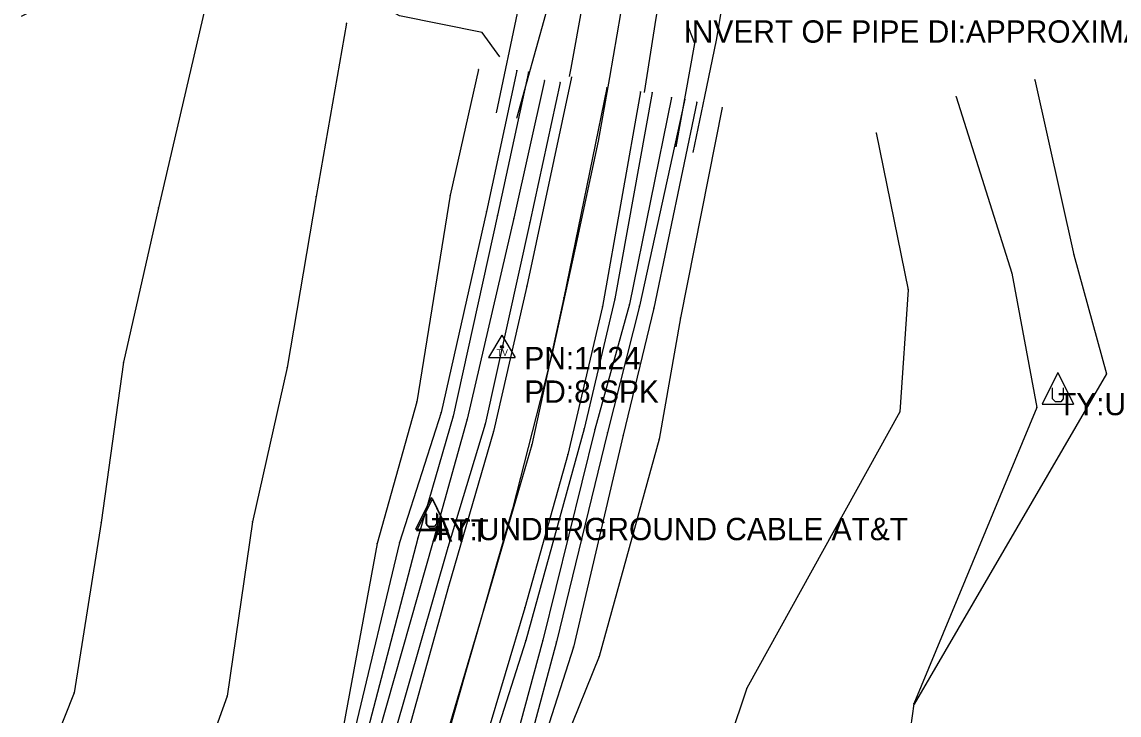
# Model space of a CAD drawing. Extents: x 976456 to 985170, y 1525951 to 1527080.
# Drawn here: x 977697.7 to 977943.1, y 1526175.1 to 1526330.3 of the extents above; entities that cross this region are included whole.
import ezdxf

# ---------------------------------------------------------------- set-up
doc = ezdxf.new("R2010")
doc.units = 0
for name, color, linetype in [('S_BREAKLINE', 7, 'Continuous'), ('S_CROSS_DRAIN_ANNOT', 7, 'Continuous'), ('S_DITCHLINE', 7, 'Continuous'), ('S_EDGE_PAVEMENT', 7, 'Continuous'), ('S_GRD_PT_SYM', 7, 'Continuous'), ('S_PAVEMENT_CROWN', 7, 'Continuous'), ('S_RDW_PT_SYM', 7, 'Continuous'), ('S_SECONDARY_CTL', 7, 'Continuous'), ('S_SECONDARY_CTL_ANNOT', 7, 'Continuous'), ('S_UNDERGROUND_CABLE', 7, 'Continuous'), ('S_UTILITY_POLE_ANNOT', 7, 'Continuous')]:
    doc.layers.add(name, color=color, linetype=linetype)

msp = doc.modelspace()

# ---------------------------------------------------------------- linework, layer by layer
at = {"layer": 'S_BREAKLINE'}
for p, q in [((977740.93, 1526343.34), (977728.22, 1526288.65)), ((977770.28, 1526329.98), (977763.49, 1526291.2)), ((977799.79, 1526319.61), (977793.5, 1526291.46)), ((977814.56, 1526317.14), (977807.69, 1526286.32)), ((977818.08, 1526316.7), (977811.28, 1526285.4)), ((977924.29, 1526317.31), (977933.02, 1526278.16)), ((977838.69, 1526314.51), (977830.29, 1526268.27)), ((977843.01, 1526313.39), (977833.6, 1526267.06)), ((977906.65, 1526313.53), (977919.15, 1526274.05)), ((977854.34, 1526311.09), (977845, 1526264.01)), ((977888.81, 1526305.43), (977895.95, 1526270.32)), ((977763.49, 1526291.2), (977756.99, 1526252.94)), ((977793.5, 1526291.46), (977786.04, 1526245.22)), ((977728.22, 1526288.65), (977720.44, 1526254.08)), ((977807.69, 1526286.32), (977797.28, 1526241.33)), ((977811.28, 1526285.4), (977801.34, 1526240.24)), ((977933.02, 1526278.16), (977940.3, 1526251.52)), ((977919.15, 1526274.05), (977924.73, 1526243.96)), ((977895.95, 1526270.32), (977894.08, 1526242.98)), ((977830.29, 1526268.27), (977823.44, 1526239.18)), ((977833.6, 1526267.06), (977825.83, 1526239.07)), ((977845, 1526264.01), (977840.27, 1526236.87)), ((977720.44, 1526254.08), (977715.44, 1526218.25)), ((977756.99, 1526252.94), (977749.27, 1526218.38)), ((977940.3, 1526251.52), (977897.24, 1526177.52)), ((977786.04, 1526245.22), (977777.15, 1526213.51)), ((977894.08, 1526242.98), (977859.86, 1526181.11)), ((977924.73, 1526243.96), (977897.18, 1526177.64)), ((977797.28, 1526241.33), (977789.7, 1526214.07)), ((977801.34, 1526240.24), (977792.98, 1526212.6)), ((977823.44, 1526239.18), (977810.43, 1526191.8)), ((977825.83, 1526239.07), (977814.18, 1526191.86)), ((977840.27, 1526236.87), (977826.79, 1526188.22)), ((977715.44, 1526218.25), (977709.35, 1526180.08)), ((977749.27, 1526218.38), (977743.64, 1526179.35)), ((977777.15, 1526213.51), (977769.64, 1526172.7)), ((977789.7, 1526214.07), (977777.52, 1526171.23)), ((977792.98, 1526212.6), (977780.89, 1526170.5)), ((977810.43, 1526191.8), (977800.3, 1526159.99)), ((977814.18, 1526191.86), (977805.18, 1526158.42)), ((977826.79, 1526188.22), (977813.75, 1526155.87)), ((977709.35, 1526180.08), (977700.67, 1526158.25)), ((977743.64, 1526179.35), (977728.46, 1526137.39)), ((977859.86, 1526181.11), (977847.11, 1526143.36)), ((977897.18, 1526177.64), (977890.95, 1526132.04))]:
    msp.add_line(p, q, dxfattribs=at)
at = {"layer": 'S_DITCHLINE'}
for p, q in [((977808.43, 1526319.39), (977801.58, 1526287.81)), ((977810.99, 1526319.02), (977804.09, 1526287)), ((977845.99, 1526312.97), (977835.84, 1526266.64)), ((977848.65, 1526312.28), (977839.04, 1526266.2)), ((977801.58, 1526287.81), (977791.47, 1526242.86)), ((977804.09, 1526287), (977794.15, 1526242)), ((977835.84, 1526266.64), (977828.71, 1526238.39)), ((977839.04, 1526266.2), (977832.21, 1526237.74)), ((977791.47, 1526242.86), (977782.13, 1526213.71)), ((977794.15, 1526242), (977786.27, 1526214.72)), ((977828.71, 1526238.39), (977817.24, 1526191.51)), ((977832.21, 1526237.74), (977821.09, 1526190.3)), ((977782.13, 1526213.71), (977772.23, 1526172.23)), ((977786.27, 1526214.72), (977775.04, 1526171.91)), ((977817.24, 1526191.51), (977808, 1526157.14)), ((977821.09, 1526190.3), (977810.22, 1526156.39))]:
    msp.add_line(p, q, dxfattribs=at)
for points in [[(977803.87, 1526309.92), (977808.88, 1526333.69), (977806.74, 1526348.14), (977807.54, 1526357.7), (977814.88, 1526374.06), (977815.09, 1526389.76), (977815.3, 1526405.46), (977801.81, 1526425), (977786.16, 1526424.94), (977770.5, 1526424.88), (977748.75, 1526425.18), (977727.01, 1526425.48), (977707.82, 1526425.38), (977688.64, 1526425.27)], [(977808.39, 1526308.74), (977814.91, 1526332.03), (977815.86, 1526349.35), (977820.11, 1526372.61), (977821.12, 1526388.66), (977822.13, 1526404.71), (977822, 1526423.32), (977823.34, 1526426.37)], [(977847.83, 1526301.04), (977850.45, 1526313.6), (977853.06, 1526326.17), (977856.57, 1526347.16), (977858.63, 1526348.63), (977872.94, 1526348.52), (977887.25, 1526348.41), (977896.12, 1526353.4), (977890.63, 1526370.24), (977885.14, 1526387.07), (977884.92, 1526404.81), (977884.08, 1526411.28), (977894.26, 1526418.08)], [(977804.61, 1526322.43), (977800.62, 1526327.94), (977782.14, 1526331.65), (977768.39, 1526339.53), (977759.99, 1526350.97), (977737.1, 1526355.06), (977725.38, 1526353.03), (977712.6, 1526339), (977697.5, 1526331.47)], [(977844.05, 1526302.32), (977848.21, 1526325.48), (977846.87, 1526328.85)]]:
    msp.add_lwpolyline(points, dxfattribs=at)
at = {"layer": 'S_EDGE_PAVEMENT'}
for p, q in [((977820.64, 1526317.93), (977810.64, 1526271.13)), ((977836.09, 1526314.62), (977827.56, 1526266.54)), ((977810.64, 1526271.13), (977803.17, 1526238.56)), ((977827.56, 1526266.54), (977819.84, 1526233.45)), ((977803.17, 1526238.56), (977793.09, 1526203.88)), ((977819.84, 1526233.45), (977810.19, 1526199.14)), ((977793.09, 1526203.88), (977780.86, 1526159.93)), ((977810.19, 1526199.14), (977796.72, 1526154.04))]:
    msp.add_line(p, q, dxfattribs=at)
for points in [[(977806.37, 1526482.87), (977820.39, 1526466.97), (977828.21, 1526455.31), (977832.92, 1526442.85), (977832.99, 1526420.15), (977832.01, 1526406.85), (977831.04, 1526393.54), (977829.31, 1526379.42), (977827.58, 1526365.3), (977826.83, 1526352.54), (977823.07, 1526334.32), (977820.44, 1526319.89), (977820.11, 1526318.04)], [(977836.99, 1526314.48), (977839.59, 1526331.09), (977843.36, 1526352.86), (977845.38, 1526367.38), (977847.41, 1526381.91), (977848.61, 1526400.06), (977849.81, 1526418.21), (977851.7, 1526441.64), (977857.03, 1526454.35), (977864.88, 1526466), (977877.36, 1526477.82)]]:
    msp.add_lwpolyline(points, dxfattribs=at)
at = {"layer": 'S_GRD_PT_SYM'}
for points in [[(977770.28, 1526329.98), (977770.28, 1526330.03), (977770.28, 1526329.98), (977770.23, 1526329.98), (977770.28, 1526329.98), (977770.28, 1526329.93), (977770.28, 1526329.98), (977770.33, 1526329.98)], [(977799.79, 1526319.61), (977799.79, 1526319.66), (977799.79, 1526319.61), (977799.74, 1526319.61), (977799.79, 1526319.61), (977799.79, 1526319.56), (977799.79, 1526319.61), (977799.84, 1526319.61)], [(977808.43, 1526319.39), (977808.43, 1526319.44), (977808.43, 1526319.39), (977808.38, 1526319.39), (977808.43, 1526319.39), (977808.43, 1526319.34), (977808.43, 1526319.39), (977808.48, 1526319.39)], [(977810.99, 1526319.02), (977810.99, 1526319.07), (977810.99, 1526319.02), (977810.94, 1526319.02), (977810.99, 1526319.02), (977810.99, 1526318.97), (977810.99, 1526319.02), (977811.04, 1526319.02)], [(977814.56, 1526317.14), (977814.56, 1526317.19), (977814.56, 1526317.14), (977814.51, 1526317.14), (977814.56, 1526317.14), (977814.56, 1526317.09), (977814.56, 1526317.14), (977814.61, 1526317.14)], [(977818.08, 1526316.7), (977818.08, 1526316.75), (977818.08, 1526316.7), (977818.03, 1526316.7), (977818.08, 1526316.7), (977818.08, 1526316.65), (977818.08, 1526316.7), (977818.13, 1526316.7)], [(977924.29, 1526317.31), (977924.29, 1526317.36), (977924.29, 1526317.31), (977924.24, 1526317.31), (977924.29, 1526317.31), (977924.29, 1526317.26), (977924.29, 1526317.31), (977924.34, 1526317.31)], [(977838.69, 1526314.51), (977838.69, 1526314.56), (977838.69, 1526314.51), (977838.64, 1526314.51), (977838.69, 1526314.51), (977838.69, 1526314.46), (977838.69, 1526314.51), (977838.74, 1526314.51)], [(977843.01, 1526313.39), (977843.01, 1526313.44), (977843.01, 1526313.39), (977842.96, 1526313.39), (977843.01, 1526313.39), (977843.01, 1526313.34), (977843.01, 1526313.39), (977843.06, 1526313.39)], [(977845.99, 1526312.97), (977845.99, 1526313.02), (977845.99, 1526312.97), (977845.94, 1526312.97), (977845.99, 1526312.97), (977845.99, 1526312.92), (977845.99, 1526312.97), (977846.04, 1526312.97)], [(977848.65, 1526312.28), (977848.65, 1526312.33), (977848.65, 1526312.28), (977848.6, 1526312.28), (977848.65, 1526312.28), (977848.65, 1526312.23), (977848.65, 1526312.28), (977848.7, 1526312.28)], [(977906.65, 1526313.53), (977906.65, 1526313.58), (977906.65, 1526313.53), (977906.6, 1526313.53), (977906.65, 1526313.53), (977906.65, 1526313.48), (977906.65, 1526313.53), (977906.7, 1526313.53)], [(977854.34, 1526311.09), (977854.34, 1526311.14), (977854.34, 1526311.09), (977854.29, 1526311.09), (977854.34, 1526311.09), (977854.34, 1526311.04), (977854.34, 1526311.09), (977854.39, 1526311.09)], [(977888.81, 1526305.43), (977888.81, 1526305.48), (977888.81, 1526305.43), (977888.76, 1526305.43), (977888.81, 1526305.43), (977888.81, 1526305.38), (977888.81, 1526305.43), (977888.86, 1526305.43)], [(977763.49, 1526291.2), (977763.49, 1526291.25), (977763.49, 1526291.2), (977763.44, 1526291.2), (977763.49, 1526291.2), (977763.49, 1526291.15), (977763.49, 1526291.2), (977763.54, 1526291.2)], [(977793.5, 1526291.46), (977793.5, 1526291.51), (977793.5, 1526291.46), (977793.45, 1526291.46), (977793.5, 1526291.46), (977793.5, 1526291.41), (977793.5, 1526291.46), (977793.55, 1526291.46)], [(977728.22, 1526288.65), (977728.22, 1526288.7), (977728.22, 1526288.65), (977728.17, 1526288.65), (977728.22, 1526288.65), (977728.22, 1526288.6), (977728.22, 1526288.65), (977728.27, 1526288.65)], [(977801.58, 1526287.81), (977801.58, 1526287.86), (977801.58, 1526287.81), (977801.53, 1526287.81), (977801.58, 1526287.81), (977801.58, 1526287.76), (977801.58, 1526287.81), (977801.63, 1526287.81)], [(977804.09, 1526287), (977804.09, 1526287.05), (977804.09, 1526287), (977804.04, 1526287), (977804.09, 1526287), (977804.09, 1526286.95), (977804.09, 1526287), (977804.14, 1526287)], [(977807.69, 1526286.32), (977807.69, 1526286.37), (977807.69, 1526286.32), (977807.64, 1526286.32), (977807.69, 1526286.32), (977807.69, 1526286.27), (977807.69, 1526286.32), (977807.74, 1526286.32)], [(977811.28, 1526285.4), (977811.28, 1526285.45), (977811.28, 1526285.4), (977811.23, 1526285.4), (977811.28, 1526285.4), (977811.28, 1526285.35), (977811.28, 1526285.4), (977811.33, 1526285.4)], [(977933.02, 1526278.16), (977933.02, 1526278.21), (977933.02, 1526278.16), (977932.97, 1526278.16), (977933.02, 1526278.16), (977933.02, 1526278.11), (977933.02, 1526278.16), (977933.07, 1526278.16)], [(977919.15, 1526274.05), (977919.15, 1526274.1), (977919.15, 1526274.05), (977919.1, 1526274.05), (977919.15, 1526274.05), (977919.15, 1526274), (977919.15, 1526274.05), (977919.21, 1526274.05)], [(977895.95, 1526270.32), (977895.95, 1526270.37), (977895.95, 1526270.32), (977895.9, 1526270.32), (977895.95, 1526270.32), (977895.95, 1526270.27), (977895.95, 1526270.32), (977896, 1526270.32)], [(977830.29, 1526268.27), (977830.29, 1526268.32), (977830.29, 1526268.27), (977830.24, 1526268.27), (977830.29, 1526268.27), (977830.29, 1526268.22), (977830.29, 1526268.27), (977830.34, 1526268.27)], [(977833.6, 1526267.06), (977833.6, 1526267.11), (977833.6, 1526267.06), (977833.55, 1526267.06), (977833.6, 1526267.06), (977833.6, 1526267.01), (977833.6, 1526267.06), (977833.65, 1526267.06)], [(977835.84, 1526266.64), (977835.84, 1526266.69), (977835.84, 1526266.64), (977835.79, 1526266.64), (977835.84, 1526266.64), (977835.84, 1526266.59), (977835.84, 1526266.64), (977835.89, 1526266.64)], [(977839.04, 1526266.2), (977839.04, 1526266.25), (977839.04, 1526266.2), (977838.99, 1526266.2), (977839.04, 1526266.2), (977839.04, 1526266.15), (977839.04, 1526266.2), (977839.09, 1526266.2)], [(977845, 1526264.01), (977845, 1526264.06), (977845, 1526264.01), (977844.95, 1526264.01), (977845, 1526264.01), (977845, 1526263.96), (977845, 1526264.01), (977845.05, 1526264.01)], [(977720.44, 1526254.08), (977720.44, 1526254.13), (977720.44, 1526254.08), (977720.39, 1526254.08), (977720.44, 1526254.08), (977720.44, 1526254.03), (977720.44, 1526254.08), (977720.49, 1526254.08)], [(977756.99, 1526252.94), (977756.99, 1526252.99), (977756.99, 1526252.94), (977756.94, 1526252.94), (977756.99, 1526252.94), (977756.99, 1526252.89), (977756.99, 1526252.94), (977757.04, 1526252.94)], [(977940.3, 1526251.52), (977940.3, 1526251.57), (977940.3, 1526251.52), (977940.25, 1526251.52), (977940.3, 1526251.52), (977940.3, 1526251.47), (977940.3, 1526251.52), (977940.35, 1526251.52)], [(977786.04, 1526245.22), (977786.04, 1526245.27), (977786.04, 1526245.22), (977785.99, 1526245.22), (977786.04, 1526245.22), (977786.04, 1526245.17), (977786.04, 1526245.22), (977786.09, 1526245.22)], [(977791.47, 1526242.86), (977791.47, 1526242.91), (977791.47, 1526242.86), (977791.42, 1526242.86), (977791.47, 1526242.86), (977791.47, 1526242.81), (977791.47, 1526242.86), (977791.52, 1526242.86)], [(977894.08, 1526242.98), (977894.08, 1526243.03), (977894.08, 1526242.98), (977894.03, 1526242.98), (977894.08, 1526242.98), (977894.08, 1526242.93), (977894.08, 1526242.98), (977894.13, 1526242.98)], [(977924.73, 1526243.96), (977924.73, 1526244.01), (977924.73, 1526243.96), (977924.68, 1526243.96), (977924.73, 1526243.96), (977924.73, 1526243.91), (977924.73, 1526243.96), (977924.78, 1526243.96)], [(977794.15, 1526242), (977794.15, 1526242.05), (977794.15, 1526242), (977794.1, 1526242), (977794.15, 1526242), (977794.15, 1526241.95), (977794.15, 1526242), (977794.2, 1526242)], [(977797.28, 1526241.33), (977797.28, 1526241.38), (977797.28, 1526241.33), (977797.23, 1526241.33), (977797.28, 1526241.33), (977797.28, 1526241.28), (977797.28, 1526241.33), (977797.33, 1526241.33)], [(977801.34, 1526240.24), (977801.34, 1526240.29), (977801.34, 1526240.24), (977801.29, 1526240.24), (977801.34, 1526240.24), (977801.34, 1526240.19), (977801.34, 1526240.24), (977801.39, 1526240.24)], [(977823.44, 1526239.18), (977823.44, 1526239.23), (977823.44, 1526239.18), (977823.39, 1526239.18), (977823.44, 1526239.18), (977823.44, 1526239.13), (977823.44, 1526239.18), (977823.49, 1526239.18)], [(977825.83, 1526239.07), (977825.83, 1526239.12), (977825.83, 1526239.07), (977825.78, 1526239.07), (977825.83, 1526239.07), (977825.83, 1526239.02), (977825.83, 1526239.07), (977825.88, 1526239.07)], [(977828.71, 1526238.39), (977828.71, 1526238.44), (977828.71, 1526238.39), (977828.66, 1526238.39), (977828.71, 1526238.39), (977828.71, 1526238.34), (977828.71, 1526238.39), (977828.76, 1526238.39)], [(977832.21, 1526237.74), (977832.21, 1526237.79), (977832.21, 1526237.74), (977832.16, 1526237.74), (977832.21, 1526237.74), (977832.21, 1526237.69), (977832.21, 1526237.74), (977832.26, 1526237.74)], [(977840.27, 1526236.87), (977840.27, 1526236.92), (977840.27, 1526236.87), (977840.22, 1526236.87), (977840.27, 1526236.87), (977840.27, 1526236.82), (977840.27, 1526236.87), (977840.32, 1526236.87)], [(977715.44, 1526218.25), (977715.44, 1526218.3), (977715.44, 1526218.25), (977715.39, 1526218.25), (977715.44, 1526218.25), (977715.44, 1526218.2), (977715.44, 1526218.25), (977715.49, 1526218.25)], [(977749.27, 1526218.38), (977749.27, 1526218.43), (977749.27, 1526218.38), (977749.22, 1526218.38), (977749.27, 1526218.38), (977749.27, 1526218.33), (977749.27, 1526218.38), (977749.32, 1526218.38)], [(977777.15, 1526213.51), (977777.15, 1526213.56), (977777.15, 1526213.51), (977777.1, 1526213.51), (977777.15, 1526213.51), (977777.15, 1526213.46), (977777.15, 1526213.51), (977777.2, 1526213.51)], [(977782.13, 1526213.71), (977782.13, 1526213.76), (977782.13, 1526213.71), (977782.08, 1526213.71), (977782.13, 1526213.71), (977782.13, 1526213.66), (977782.13, 1526213.71), (977782.18, 1526213.71)], [(977786.27, 1526214.72), (977786.27, 1526214.77), (977786.27, 1526214.72), (977786.22, 1526214.72), (977786.27, 1526214.72), (977786.27, 1526214.67), (977786.27, 1526214.72), (977786.32, 1526214.72)], [(977789.7, 1526214.07), (977789.7, 1526214.12), (977789.7, 1526214.07), (977789.65, 1526214.07), (977789.7, 1526214.07), (977789.7, 1526214.02), (977789.7, 1526214.07), (977789.75, 1526214.07)], [(977792.98, 1526212.6), (977792.98, 1526212.65), (977792.98, 1526212.6), (977792.93, 1526212.6), (977792.98, 1526212.6), (977792.98, 1526212.55), (977792.98, 1526212.6), (977793.03, 1526212.6)], [(977810.43, 1526191.8), (977810.43, 1526191.85), (977810.43, 1526191.8), (977810.38, 1526191.8), (977810.43, 1526191.8), (977810.43, 1526191.75), (977810.43, 1526191.8), (977810.48, 1526191.8)], [(977814.18, 1526191.86), (977814.18, 1526191.91), (977814.18, 1526191.86), (977814.13, 1526191.86), (977814.18, 1526191.86), (977814.18, 1526191.81), (977814.18, 1526191.86), (977814.23, 1526191.86)], [(977817.24, 1526191.51), (977817.24, 1526191.56), (977817.24, 1526191.51), (977817.19, 1526191.51), (977817.24, 1526191.51), (977817.24, 1526191.46), (977817.24, 1526191.51), (977817.29, 1526191.51)], [(977821.09, 1526190.3), (977821.09, 1526190.35), (977821.09, 1526190.3), (977821.04, 1526190.3), (977821.09, 1526190.3), (977821.09, 1526190.26), (977821.09, 1526190.3), (977821.14, 1526190.3)], [(977826.79, 1526188.22), (977826.79, 1526188.27), (977826.79, 1526188.22), (977826.74, 1526188.22), (977826.79, 1526188.22), (977826.79, 1526188.17), (977826.79, 1526188.22), (977826.84, 1526188.22)], [(977709.35, 1526180.08), (977709.35, 1526180.13), (977709.35, 1526180.08), (977709.3, 1526180.08), (977709.35, 1526180.08), (977709.35, 1526180.03), (977709.35, 1526180.08), (977709.4, 1526180.08)], [(977743.64, 1526179.35), (977743.64, 1526179.41), (977743.64, 1526179.35), (977743.59, 1526179.35), (977743.64, 1526179.35), (977743.64, 1526179.3), (977743.64, 1526179.35), (977743.69, 1526179.35)], [(977859.86, 1526181.11), (977859.86, 1526181.16), (977859.86, 1526181.11), (977859.81, 1526181.11), (977859.86, 1526181.11), (977859.86, 1526181.06), (977859.86, 1526181.11), (977859.91, 1526181.11)], [(977897.18, 1526177.64), (977897.18, 1526177.69), (977897.18, 1526177.64), (977897.13, 1526177.64), (977897.18, 1526177.64), (977897.18, 1526177.59), (977897.18, 1526177.64), (977897.23, 1526177.64)], [(977897.24, 1526177.52), (977897.24, 1526177.57), (977897.24, 1526177.52), (977897.19, 1526177.52), (977897.24, 1526177.52), (977897.24, 1526177.47), (977897.24, 1526177.52), (977897.29, 1526177.52)]]:
    msp.add_lwpolyline(points, dxfattribs=at)
at = {"layer": 'S_PAVEMENT_CROWN'}
for p, q in [((977828.54, 1526315.5), (977818.93, 1526268.5)), ((977818.93, 1526268.5), (977811.73, 1526235.64)), ((977811.73, 1526235.64), (977801.82, 1526201.55)), ((977801.82, 1526201.55), (977788.73, 1526157.34))]:
    msp.add_line(p, q, dxfattribs=at)
msp.add_lwpolyline([(977844.21, 1526481.41), (977843.54, 1526464.03), (977842.87, 1526446.65), (977841.9, 1526432.77), (977840.93, 1526418.89), (977839.74, 1526405.83), (977838.55, 1526392.78), (977837.18, 1526378.23), (977835.8, 1526363.67), (977833.69, 1526347.92), (977831.58, 1526332.17), (977829.1, 1526317.87), (977826.61, 1526303.58), (977821.41, 1526279.65), (977816.2, 1526255.72), (977811.81, 1526238.51), (977807.43, 1526221.29), (977803.88, 1526208.91), (977800.34, 1526196.52), (977796.79, 1526184.14), (977793.25, 1526171.75), (977786.88, 1526150.07), (977780.5, 1526128.38)], dxfattribs=at)
at = {"layer": 'S_RDW_PT_SYM'}
for points in [[(977820.64, 1526317.93), (977820.64, 1526317.98), (977820.64, 1526317.93), (977820.59, 1526317.93), (977820.64, 1526317.93), (977820.64, 1526317.88), (977820.64, 1526317.93), (977820.69, 1526317.93)], [(977828.54, 1526315.5), (977828.54, 1526315.55), (977828.54, 1526315.5), (977828.49, 1526315.5), (977828.54, 1526315.5), (977828.54, 1526315.45), (977828.54, 1526315.5), (977828.59, 1526315.5)], [(977836.09, 1526314.62), (977836.09, 1526314.67), (977836.09, 1526314.62), (977836.04, 1526314.62), (977836.09, 1526314.62), (977836.09, 1526314.57), (977836.09, 1526314.62), (977836.14, 1526314.62)], [(977810.64, 1526271.13), (977810.64, 1526271.18), (977810.64, 1526271.13), (977810.59, 1526271.13), (977810.64, 1526271.13), (977810.64, 1526271.08), (977810.64, 1526271.13), (977810.69, 1526271.13)], [(977818.93, 1526268.5), (977818.93, 1526268.55), (977818.93, 1526268.5), (977818.88, 1526268.5), (977818.93, 1526268.5), (977818.93, 1526268.45), (977818.93, 1526268.5), (977818.98, 1526268.5)], [(977827.56, 1526266.54), (977827.56, 1526266.59), (977827.56, 1526266.54), (977827.51, 1526266.54), (977827.56, 1526266.54), (977827.56, 1526266.49), (977827.56, 1526266.54), (977827.61, 1526266.54)], [(977803.17, 1526238.56), (977803.17, 1526238.61), (977803.17, 1526238.56), (977803.12, 1526238.56), (977803.17, 1526238.56), (977803.17, 1526238.51), (977803.17, 1526238.56), (977803.22, 1526238.56)], [(977811.73, 1526235.64), (977811.73, 1526235.69), (977811.73, 1526235.64), (977811.68, 1526235.64), (977811.73, 1526235.64), (977811.73, 1526235.59), (977811.73, 1526235.64), (977811.78, 1526235.64)], [(977819.84, 1526233.45), (977819.84, 1526233.5), (977819.84, 1526233.45), (977819.79, 1526233.45), (977819.84, 1526233.45), (977819.84, 1526233.4), (977819.84, 1526233.45), (977819.89, 1526233.45)], [(977793.09, 1526203.88), (977793.09, 1526203.93), (977793.09, 1526203.88), (977793.04, 1526203.88), (977793.09, 1526203.88), (977793.09, 1526203.83), (977793.09, 1526203.88), (977793.14, 1526203.88)], [(977801.82, 1526201.55), (977801.82, 1526201.6), (977801.82, 1526201.55), (977801.77, 1526201.55), (977801.82, 1526201.55), (977801.82, 1526201.5), (977801.82, 1526201.55), (977801.87, 1526201.55)], [(977810.19, 1526199.14), (977810.19, 1526199.19), (977810.19, 1526199.14), (977810.14, 1526199.14), (977810.19, 1526199.14), (977810.19, 1526199.09), (977810.19, 1526199.14), (977810.24, 1526199.14)]]:
    msp.add_lwpolyline(points, dxfattribs=at)
at = {"layer": 'S_SECONDARY_CTL'}
for p, q in [((977805.07, 1526260.13), (977802.06, 1526255.18)), ((977805.07, 1526260.13), (977808.02, 1526255.18)), ((977802.06, 1526255.18), (977808.02, 1526255.18))]:
    msp.add_line(p, q, dxfattribs=at)
for radius in [0.311, 0.183, 0.103]:
    msp.add_circle((977805.07, 1526257.52), radius, dxfattribs=at)
at = {"layer": 'S_UNDERGROUND_CABLE'}
for p, q in [((977929.44, 1526251.77), (977925.92, 1526244.68)), ((977929.44, 1526251.77), (977932.93, 1526244.68)), ((977928.24, 1526245.92), (977928.24, 1526248.36)), ((977930.6, 1526248.36), (977930.6, 1526245.92)), ((977928.86, 1526245.26), (977928.24, 1526245.92)), ((977930.06, 1526245.26), (977928.86, 1526245.26)), ((977930.6, 1526245.92), (977930.06, 1526245.26)), ((977925.92, 1526244.68), (977932.93, 1526244.68)), ((977789.28, 1526223.8), (977785.76, 1526216.71)), ((977789.5, 1526223.49), (977785.97, 1526216.4)), ((977789.28, 1526223.8), (977792.77, 1526216.71)), ((977789.5, 1526223.49), (977792.99, 1526216.4)), ((977788.08, 1526217.95), (977788.08, 1526220.39)), ((977788.3, 1526217.64), (977788.3, 1526220.08)), ((977790.45, 1526220.39), (977790.45, 1526217.95)), ((977790.66, 1526220.08), (977790.66, 1526217.64)), ((977785.76, 1526216.71), (977792.77, 1526216.71)), ((977785.97, 1526216.4), (977792.99, 1526216.4)), ((977788.7, 1526217.29), (977788.08, 1526217.95)), ((977788.92, 1526216.98), (977788.3, 1526217.64)), ((977789.9, 1526217.29), (977788.7, 1526217.29)), ((977790.12, 1526216.98), (977788.92, 1526216.98)), ((977790.45, 1526217.95), (977789.9, 1526217.29)), ((977790.66, 1526217.64), (977790.12, 1526216.98))]:
    msp.add_line(p, q, dxfattribs=at)

# ---------------------------------------------------------------- texts
at = {"layer": 'S_CROSS_DRAIN_ANNOT'}
msp.add_text('INVERT OF PIPE DI:APPROXIMATE 1', height=5, dxfattribs=at).set_placement((977845.69, 1526325.63))
at = {"layer": 'S_SECONDARY_CTL'}
msp.add_text('TV', height=1.5, rotation=360, dxfattribs=at).set_placement((977803.86, 1526255.51))
at = {"layer": 'S_SECONDARY_CTL_ANNOT'}
for s, p in [('PN:1124', (977810.07, 1526252.52)), ('PD:8 SPK', (977810.07, 1526245.02))]:
    msp.add_text(s, height=5, dxfattribs=at).set_placement(p)
at = {"layer": 'S_UTILITY_POLE_ANNOT'}
for s, p in [('TY:UNDERGROUND CABLE', (977929.44, 1526242.24)), ('TY:UNDERGROUND CABLE AT&T', (977789.28, 1526214.26)), ('ATT', (977789.5, 1526213.96))]:
    msp.add_text(s, height=5, dxfattribs=at).set_placement(p)

doc.saveas('drawing.dxf')
